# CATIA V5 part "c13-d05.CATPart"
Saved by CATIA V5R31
Part number: Part1
Bounding box of the stored display mesh (mm): x -62.5 to 62.5, y -75 to 75, z 0 to 20
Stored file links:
  D:\PROJECTS\Project 2021\US EDITION\CATIA V5 6R 2021\Resources\Part Files\c13_catia_v5_6r2021_prt\c13_catia_v5-6r2021_figr_13-22 & 24\c13-d05.CATPart
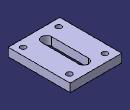
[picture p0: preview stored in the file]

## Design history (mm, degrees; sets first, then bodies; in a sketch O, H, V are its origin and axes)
Body1 (main body)
  Sketch1 on xy-plane, origin (0, 0, 0), H (1, 0, 0), V (0, 1, 0)
    line L1 (62.5, 75) -> (62.5, -75)
    line L2 (62.5, -75) -> (-62.5, -75)
    line L3 (-62.5, -75) -> (-62.5, 75)
    line L4 (-62.5, 75) -> (62.5, 75)
    length L1 = 150
    length L2 = 125
    vertical: L1 V, L3 V
    horizontal: L2 H, L4 H
    equidistance: L1 L3 O, L2 L4 O
  Pad1: profile Sketch1, direction (0, 0, 1), length 20
  Sketch2 on face of Pad1, origin (0, 0, 20), H (1, 0, 0), V (0, 1, 0)
    construction line L1 (0, 45) -> (0, -45)
    point P1 (0, 45)
    line L2 (12, 45) -> (12, -45)
    line L3 (-12, -45) -> (-12, 45)
    arc A1 centre (0, -45) radius 12 from (12, -45) to (-12, -45) cw
    arc A2 centre (0, 45) radius 12 from (-12, 45) to (12, 45) cw
    length L1 = 90
    radius A2 = 12
    coincidence: P1 V
    vertical: L1 V
    tangency: A1 L2, A2 L2, A1 L3, A2 L3
    parallelism: L1 L2
    midpoint: O L1
  Pocket1: profile Sketch2, direction (0, 0, -1), through (limit type 3)
  Sketch3 on face of Pad1, origin (38.7626, -18.4621, 20), H (1, 0, 0), V (0, 1, 0)
    point P1 (5.7374, -38.5379)
    reference projected line E1 (-101.2626, -56.5379) -> (23.7374, -56.5379) from edge [face of Pad1 | face of Pad1]
    reference projected line E2 (23.7374, -56.5379) -> (23.7374, 93.4621) from edge [face of Pad1 | face of Pad1]
    distance P1 E1 = 18
    distance P1 E2 = 18
  Hole1: placed by Sketch3, at (44.5, -57, 20) direction (0, 0, -1), diameter 13, through (limit type 3)
  RectPattern1: of Hole1, direction 1 instances 2, spacing 86, along edge [face of Pad1 | face of Pad1] reversed, direction 2 instances 2, spacing 112, along edge [face of Pad1 | face of Pad1]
